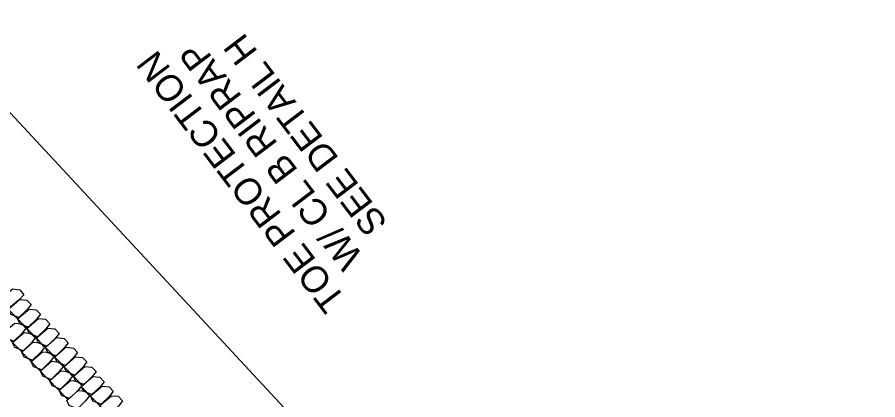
# Model space of a CAD drawing. Extents: x 465700 to 483515, y 488970 to 507540.
# Drawn here: x 476504.7 to 476667, y 500817.8 to 500890 of the extents above; entities that cross this region are included whole.
import ezdxf

# ---------------------------------------------------------------- set-up
doc = ezdxf.new("R2010")
doc.units = 0
for name, color, linetype in [('Exist Plan Preparation Watershed Blue', 7, 'Continuous'), ('Prop Erosion Embankment Toe Protection CELL', 7, 'Continuous'), ('Prop Erosion Embankment Toe Protection Label', 7, 'Continuous')]:
    doc.layers.add(name, color=color, linetype=linetype)

msp = doc.modelspace()

# ---------------------------------------------------------------- linework, layer by layer
at = {"layer": 'Exist Plan Preparation Watershed Blue'}
for points in [[(476921.2, 501693.96), (476873.97, 501665.49), (476797.54, 501630.58), (476778.04, 501586.57), (476684.08, 501524.02), (476617.13, 501430.2), (476608.09, 501344.67), (476632.2, 501297.34), (476652.85, 501202.84), (476684.48, 501113.94), (476686.07, 501079.86), (476666.3, 501048.93), (476630.01, 501028.21), (476577.87, 501021.26), (476528.03, 501006.59), (476466.6, 500992.22), (476420.26, 500966.99), (476486.96, 500889.51), (476555.03, 500816.27), (476625.62, 500745.44), (476698.65, 500677.13), (476726.48, 500652.21), (476834.31, 500555.52), (476965.29, 500641)], [(476922.43, 500477.32), (476847.82, 500543.91), (476773.22, 500610.51), (476698.65, 500677.13), (476625.62, 500745.44), (476555.03, 500816.27), (476486.96, 500889.51), (476420.26, 500966.99), (476358.7, 501042.92), (476298.67, 501122.89), (476241.47, 501204.91)], [(476965.29, 500641), (476834.31, 500555.52), (476726.48, 500652.21), (476625.62, 500745.44), (476555.03, 500816.27), (476486.96, 500889.51), (476420.26, 500966.99), (476358.7, 501042.92), (476298.67, 501122.89), (476241.47, 501204.91)]]:
    msp.add_lwpolyline(points, dxfattribs=at)
at = {"layer": 'Prop Erosion Embankment Toe Protection CELL'}
for p, q in [((476503.01, 500834.85), (476516.95, 500820.5)), ((476500.29, 500832.2), (476514.22, 500817.85)), ((476516.75, 500820.32), (476530.68, 500805.97))]:
    msp.add_line(p, q, dxfattribs=at)
for points in [[(476505.94, 500837.62), (476505.12, 500836.73), (476503.49, 500835.34), (476501.98, 500836.03), (476501.6, 500837.01), (476503.87, 500838.75), (476505.16, 500838.54), (476505.94, 500837.62)], [(476507.3, 500835.74), (476506.55, 500834.8), (476505, 500833.3), (476503.46, 500833.89), (476503.01, 500834.85), (476505.16, 500836.73), (476506.48, 500836.58), (476507.3, 500835.74)], [(476509.04, 500833.95), (476508.31, 500832.99), (476506.76, 500831.49), (476505.2, 500832.09), (476504.75, 500833.05), (476506.92, 500834.92), (476508.24, 500834.77), (476509.04, 500833.95)], [(476506.32, 500831.3), (476505.58, 500830.34), (476504.04, 500828.84), (476502.47, 500829.45), (476502.03, 500830.41), (476504.19, 500832.27), (476505.52, 500832.12), (476506.32, 500831.3)], [(476510.8, 500832.14), (476510.06, 500831.17), (476508.52, 500829.68), (476506.96, 500830.28), (476506.51, 500831.24), (476508.68, 500833.1), (476509.98, 500832.98), (476510.8, 500832.14)], [(476508.08, 500829.49), (476507.34, 500828.53), (476505.8, 500827.03), (476504.23, 500827.63), (476503.79, 500828.6), (476505.95, 500830.46), (476507.26, 500830.33), (476508.08, 500829.49)], [(476512.56, 500830.32), (476511.81, 500829.38), (476510.26, 500827.88), (476508.72, 500828.47), (476508.27, 500829.43), (476510.42, 500831.31), (476511.73, 500831.19), (476512.56, 500830.32)], [(476509.84, 500827.68), (476509.08, 500826.73), (476507.54, 500825.24), (476505.99, 500825.82), (476505.55, 500826.78), (476507.69, 500828.66), (476509, 500828.54), (476509.84, 500827.68)], [(476514.3, 500828.53), (476513.55, 500827.59), (476512.01, 500826.09), (476510.46, 500826.68), (476510.01, 500827.64), (476512.16, 500829.52), (476513.49, 500829.37), (476514.3, 500828.53)], [(476511.58, 500825.88), (476510.82, 500824.94), (476509.28, 500823.44), (476507.73, 500824.03), (476507.29, 500824.99), (476509.44, 500826.87), (476510.76, 500826.73), (476511.58, 500825.88)], [(476516.05, 500826.74), (476515.31, 500825.78), (476513.77, 500824.28), (476512.2, 500824.88), (476511.76, 500825.85), (476513.92, 500827.71), (476515.25, 500827.56), (476516.05, 500826.74)], [(476513.32, 500824.09), (476512.58, 500823.13), (476511.04, 500821.63), (476509.47, 500822.24), (476509.03, 500823.2), (476511.2, 500825.06), (476512.52, 500824.92), (476513.32, 500824.09)], [(476517.81, 500824.93), (476517.07, 500823.97), (476515.52, 500822.47), (476513.96, 500823.07), (476513.51, 500824.03), (476515.68, 500825.89), (476516.99, 500825.77), (476517.81, 500824.93)], [(476519.57, 500823.12), (476518.81, 500822.17), (476517.27, 500820.67), (476515.72, 500821.26), (476515.27, 500822.22), (476517.42, 500824.1), (476518.73, 500823.98), (476519.57, 500823.12)], [(476515.08, 500822.28), (476514.34, 500821.32), (476512.8, 500819.82), (476511.23, 500820.43), (476510.79, 500821.39), (476512.95, 500823.25), (476514.26, 500823.12), (476515.08, 500822.28)], [(476521.04, 500821.21), (476520.28, 500820.26), (476518.74, 500818.77), (476517.2, 500819.35), (476516.75, 500820.32), (476518.9, 500822.19), (476520.22, 500822.05), (476521.04, 500821.21)], [(476516.84, 500820.47), (476516.08, 500819.52), (476514.54, 500818.03), (476512.99, 500818.61), (476512.55, 500819.58), (476514.7, 500821.45), (476516, 500821.33), (476516.84, 500820.47)], [(476522.78, 500819.41), (476522.04, 500818.45), (476520.5, 500816.95), (476518.94, 500817.56), (476518.49, 500818.52), (476520.66, 500820.38), (476521.98, 500820.24), (476522.78, 500819.41)], [(476518.32, 500818.56), (476517.56, 500817.62), (476516.02, 500816.12), (476514.47, 500816.71), (476514.02, 500817.67), (476516.17, 500819.55), (476517.5, 500819.4), (476518.32, 500818.56)], [(476524.54, 500817.6), (476523.8, 500816.64), (476522.26, 500815.14), (476520.7, 500815.75), (476520.25, 500816.71), (476522.42, 500818.57), (476523.72, 500818.45), (476524.54, 500817.6)]]:
    msp.add_lwpolyline(points, dxfattribs=at)

# ---------------------------------------------------------------- texts
at = {"layer": 'Prop Erosion Embankment Toe Protection Label'}
for s, p in [('SEE DETAIL H', (476574.69, 500851.17)), ('TOE PROTECTION', (476566.82, 500836.73)), ('W/ CL B RIPRAP', (476570.13, 500844.77))]:
    msp.add_text(s, height=5, rotation=127.2369, dxfattribs=at).set_placement(p)

doc.saveas('drawing.dxf')
